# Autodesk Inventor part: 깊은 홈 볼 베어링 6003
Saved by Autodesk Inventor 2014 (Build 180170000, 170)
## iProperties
Created: 2026-06
Part Number: 깊은 홈 볼 베어링 6003
Material: 강철, 연강
Document SubType Name: Modeling
Designer: dg
Density: 7.86 g/cm^3
Appearance: 강철
Mass: 39.0276 g
Surface Area: 48.7538 cm^2
Volume: 4.96535 cm^3
Author: jhkim
Description: 깊은 그루브 볼 베어링
Creation Date: 2026-05-29
Sending System: Autodesk Inventor 2027
Preprocessor: ST-DEVELOPER v20.1
Author: dg
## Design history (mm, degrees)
node "깊은 홈 볼 베어링 60031"
body "Solid1"
node "Solid1_1"
node "Solid1_2"
node "Solid1_3"
node "Solid1_4"
node "Solid1_5"
node "Solid1_6"
node "Solid1_7"
node "Solid1_8"
node "Solid1_9"
node "Solid1_10"
node "기준1"
node "기준2"
node "기준3"
node "기준4"
node "기준5"
node "기준6"
node "기준7"
node "기준8"
node "기준9"
node "기준10"
node "기준11"
